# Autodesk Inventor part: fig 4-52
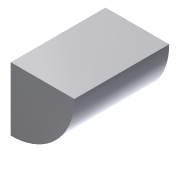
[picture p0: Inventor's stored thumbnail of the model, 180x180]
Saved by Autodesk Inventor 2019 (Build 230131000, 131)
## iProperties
Created: 2010-02
Part Number: fig 4-52
Document SubType Name: Modeling
Designer: CADSoft
Density: 1 g/cm^3
Material: Generic
Appearance: Default
Author: CADSoft
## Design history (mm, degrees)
sketch "Sketch1"
  geometry: L1 (0, 30.039)-(20.155, 30.039); L2 (20.155, 30.039)-(20.155, 0); L3 (20.155, 0)-(0, 0); L4 (0, 31.977)-(0, -5.62); 1 further point
  constraints: 8 end point, 2 point on line
revolve "Revolution1" sketch "Sketch1" stored, may be unused: angle "d0" = 90 deg
body "Solid1"
